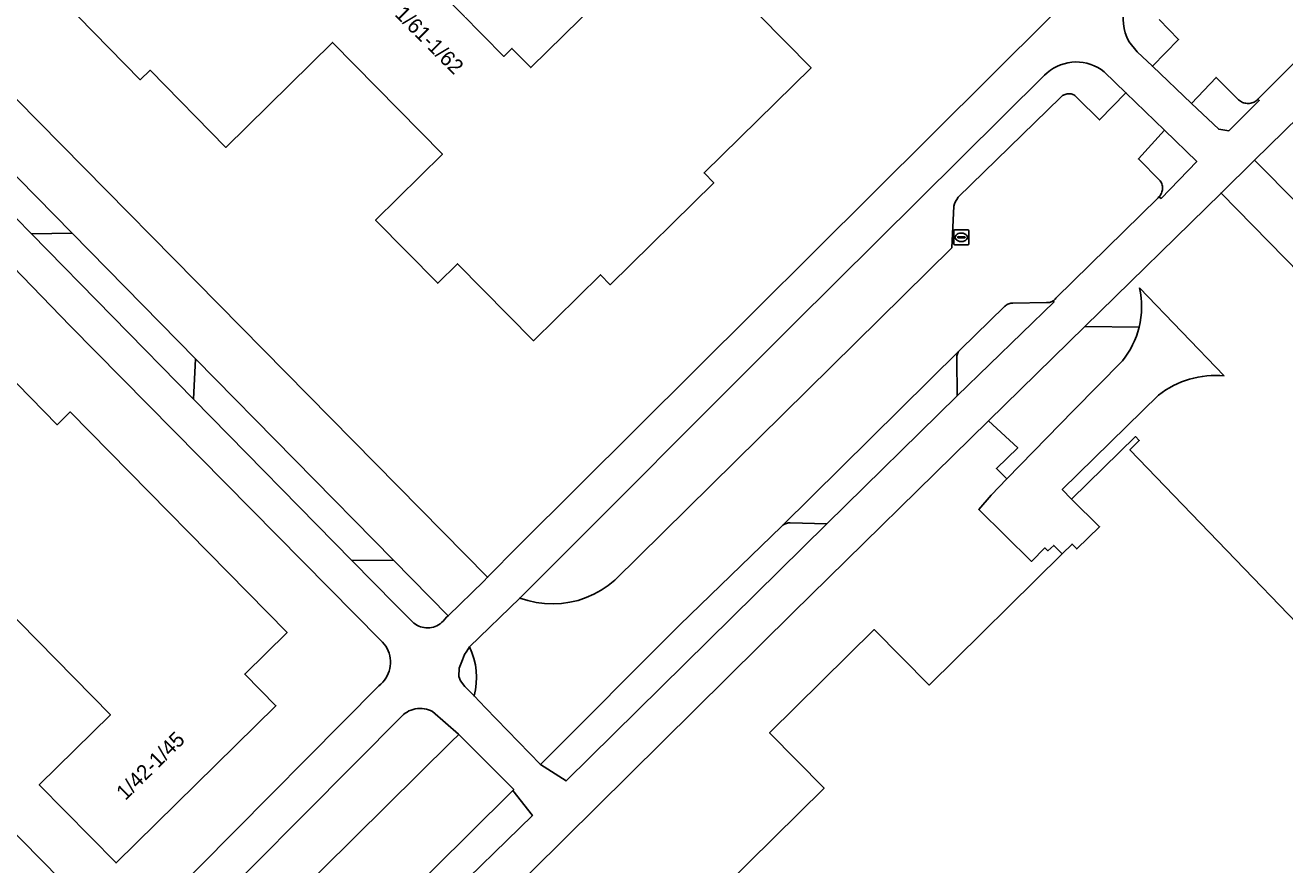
# Model space of a CAD drawing. Extents: x 162788 to 163838, y 385791 to 386523.
# Drawn here: x 163008.9 to 163092.2, y 386015.9 to 386071.5 of the extents above; entities that cross this region are included whole.
import ezdxf

# ---------------------------------------------------------------- set-up
doc = ezdxf.new("R2010")
doc.units = 0
for name, color, linetype in [('IMGEO_Berm_groen', 7, 'Continuous'), ('IMGEO_Erf', 7, 'Continuous'), ('IMGEO_Groenvoorziening', 7, 'Continuous'), ('IMGEO_Kolk', 7, 'Continuous'), ('IMGEO_Pand', 7, 'Continuous'), ('IMGEO_Pand_nummerreeks', 7, 'Continuous'), ('IMGEO_Parkeervlak_open', 7, 'Continuous'), ('IMGEO_Rijbaan_lokaal_gesloten', 7, 'Continuous'), ('IMGEO_Voetpad_gesloten', 7, 'Continuous'), ('IMGEO_Voetpad_open', 7, 'Continuous'), ('IMGEO_Woonerf_gesloten', 7, 'Continuous'), ('IMGEO_Woonerf_open', 7, 'Continuous')]:
    doc.layers.add(name, color=color, linetype=linetype)

msp = doc.modelspace()

# ---------------------------------------------------------------- linework, layer by layer
at = {"layer": 'IMGEO_Berm_groen'}
msp.add_lwpolyline([(163081.553, 386071.573), (163081.602, 386071.274), (163081.677, 386070.98), (163081.777, 386070.695), (163081.902, 386070.419), (163082.458, 386069.732), (163083.469, 386068.773), (163085.202, 386070.551), (163083.912, 386071.86)], dxfattribs=at)
for points in [[(163070.202, 386056.756), (163070.331, 386059.512), (163070.38, 386059.668), (163070.443, 386059.819), (163070.52, 386059.963), (163070.61, 386060.1), (163077.381, 386066.695), (163077.426, 386066.743), (163077.475, 386066.786), (163077.527, 386066.825), (163077.583, 386066.86), (163077.641, 386066.889), (163077.702, 386066.912), (163077.765, 386066.931), (163077.829, 386066.943), (163077.893, 386066.95), (163077.959, 386066.951), (163078.024, 386066.946), (163078.088, 386066.935), (163078.151, 386066.919), (163078.213, 386066.897), (163078.272, 386066.87), (163078.329, 386066.837), (163078.382, 386066.8), (163078.432, 386066.758), (163078.478, 386066.712), (163078.52, 386066.661), (163079.964, 386065.225), (163081.713, 386067.014), (163080.274, 386068.409), (163080.069, 386068.559), (163079.851, 386068.691), (163079.622, 386068.803), (163079.385, 386068.896), (163079.141, 386068.967), (163078.891, 386069.017), (163078.638, 386069.046), (163078.384, 386069.053), (163078.13, 386069.038), (163077.878, 386069.001), (163077.63, 386068.942), (163077.388, 386068.862), (163077.154, 386068.762), (163076.929, 386068.642), (163076.716, 386068.503), (163076.515, 386068.346), (163076.329, 386068.173), (163059.717, 386051.709), (163041.612, 386033.574), (163042.146, 386033.404), (163042.692, 386033.282), (163043.247, 386033.21), (163043.807, 386033.188), (163044.366, 386033.217), (163044.92, 386033.296), (163045.465, 386033.425), (163045.996, 386033.602), (163046.509, 386033.827), (163046.999, 386034.096), (163047.464, 386034.409), (163047.898, 386034.762)], [(163090.544, 386066.502), (163090.455, 386066.592), (163090.397, 386066.537), (163090.335, 386066.487), (163090.269, 386066.443), (163090.2, 386066.405), (163090.127, 386066.373), (163090.052, 386066.347), (163089.975, 386066.328), (163089.897, 386066.316), (163089.817, 386066.31), (163089.738, 386066.311), (163089.659, 386066.319), (163089.581, 386066.334), (163089.505, 386066.355), (163089.43, 386066.383), (163089.359, 386066.418), (163089.29, 386066.458), (163089.226, 386066.504), (163089.165, 386066.555), (163087.688, 386068.031), (163086.067, 386066.309), (163087.864, 386064.604), (163088.52, 386064.502)], [(163011.984, 386057.726), (163009.288, 386057.681), (163020.029, 386046.733), (163020.157, 386049.405)], [(163076.959, 386053.172), (163076.892, 386053.241), (163076.836, 386053.209), (163076.777, 386053.182), (163076.716, 386053.161), (163076.653, 386053.146), (163076.589, 386053.136), (163076.524, 386053.132), (163076.46, 386053.133), (163074.242, 386053.096), (163074.175, 386053.096), (163074.107, 386053.089), (163074.041, 386053.077), (163073.976, 386053.058), (163073.913, 386053.033), (163073.852, 386053.003), (163073.795, 386052.967), (163073.741, 386052.926), (163073.691, 386052.88), (163070.77, 386050.027), (163070.725, 386049.986), (163070.684, 386049.942), (163070.647, 386049.894), (163070.615, 386049.843), (163070.587, 386049.79), (163070.564, 386049.734), (163070.547, 386049.676), (163070.534, 386049.617), (163070.527, 386049.557), (163070.525, 386049.497), (163070.529, 386049.437), (163070.559, 386046.967)], [(163061.924, 386038.49), (163059.506, 386038.552), (163059.441, 386038.551), (163059.377, 386038.545), (163059.313, 386038.533), (163059.25, 386038.516), (163059.189, 386038.494), (163059.13, 386038.466), (163059.074, 386038.434), (163059.021, 386038.397), (163058.971, 386038.356), (163058.924, 386038.31), (163052.198, 386031.811), (163042.973, 386022.551), (163044.671, 386021.477)], [(163033.251, 386036.073), (163030.49, 386036.072), (163033.386, 386033.12), (163034.598, 386031.917), (163034.699, 386031.844), (163034.806, 386031.78), (163034.918, 386031.725), (163035.034, 386031.68), (163035.154, 386031.645), (163035.276, 386031.621), (163035.4, 386031.607), (163035.524, 386031.604), (163035.649, 386031.612), (163035.772, 386031.631), (163035.893, 386031.66), (163036.011, 386031.699), (163036.126, 386031.748), (163036.235, 386031.807), (163036.34, 386031.876), (163036.437, 386031.953), (163036.528, 386032.038), (163036.763, 386032.307), (163036.859, 386032.401)], [(163037.097, 386024.076), (163037.572, 386024.546), (163037.56, 386024.557), (163035.844, 386026.06), (163035.711, 386026.125), (163035.573, 386026.179), (163035.431, 386026.22), (163035.286, 386026.249), (163035.139, 386026.265), (163034.991, 386026.269), (163034.844, 386026.26), (163034.697, 386026.239), (163034.553, 386026.205), (163034.413, 386026.159), (163034.276, 386026.101), (163034.146, 386026.031), (163034.022, 386025.951), (163033.905, 386025.86), (163000.759, 385992.514), (163001.163, 385990.386), (163002.722, 385990.111), (163003.107, 385990.494), (163013.512, 386000.753)], [(163042.44, 386019.195), (163041.15, 386020.839), (163040.955, 386020.636), (163030.909, 386010.698), (163030.859, 386010.653), (163030.812, 386010.603), (163030.77, 386010.55), (163030.734, 386010.493), (163030.702, 386010.434), (163030.676, 386010.371), (163030.656, 386010.306), (163030.641, 386010.24), (163030.633, 386010.173), (163030.584, 386007.63)]]:
    msp.add_lwpolyline(points, close=True, dxfattribs=at)
at = {"layer": 'IMGEO_Erf'}
for points in [[(163144.69, 386116.333), (163116.889, 386088.826), (163094.139, 386066.379), (163090.229, 386062.548), (163093.084, 386059.675), (163106.347, 386045.615), (163117.907, 386034.052), (163120.625, 386031.361)], [(163034.593, 386105.372), (163032.927, 386102.387), (163031.643, 386100.544), (163030.645, 386099.338), (163027.569, 386096.044), (163022.475, 386091.076), (163020.687, 386089.641), (163019.2, 386088.539), (163019.01, 386088.395), (163017.057, 386087.161), (163014.761, 386086.098), (163012.296, 386085.312), (163009.878, 386084.654), (163007.401, 386084.184), (162993.768, 386081.986), (162993.461, 386081.653), (163039.475, 386034.95), (163041.516, 386037.028), (163076.704, 386072.029), (163076.476, 386072.907), (163056.429, 386093.317), (163049.21, 386100.56), (163041.713, 386107.825)], [(163036.379, 386073.667), (163040.55, 386069.424), (163041.089, 386069.954), (163042.334, 386068.688), (163053.16, 386079.329)], [(162996.592, 385991.771), (163032.285, 386027.77), (163032.418, 386027.879), (163032.54, 386028), (163032.652, 386028.132), (163032.751, 386028.272), (163032.837, 386028.421), (163032.91, 386028.577), (163032.969, 386028.739), (163033.013, 386028.905), (163033.042, 386029.075), (163033.057, 386029.246), (163033.056, 386029.418), (163033.04, 386029.59), (163033.008, 386029.759), (163032.962, 386029.925), (163032.902, 386030.086), (163032.827, 386030.241), (163032.739, 386030.389), (163032.639, 386030.529), (163032.526, 386030.659), (163032.402, 386030.778), (163011.849, 386051.6), (162989.767, 386074.455)], [(163055.694, 386073.954), (163060.889, 386068.669), (163053.807, 386061.708), (163054.447, 386061.057), (163047.59, 386054.316), (163046.949, 386054.968), (163042.506, 386050.601), (163037.494, 386055.7), (163036.181, 386054.41), (163032.067, 386058.596), (163036.488, 386062.942), (163029.212, 386070.345), (163022.152, 386063.405), (163017.14, 386068.505), (163016.498, 386067.874), (163012.383, 386072.06)], [(163122.643, 386025), (163088.018, 386060.382), (163078.994, 386051.539), (163082.592, 386051.498)], [(163082.621, 386054.105), (163088.226, 386048.292)], [(163005.665, 386050.481), (163011.004, 386045.049), (163011.867, 386045.897), (163026.216, 386031.299), (163023.413, 386028.544), (163025.477, 386026.444), (163014.893, 386016.042), (163009.811, 386021.212), (163014.518, 386025.839), (163003.657, 386036.889)], [(163083.877, 386047.013), (163077.501, 386040.771), (163078.117, 386040.121), (163082.342, 386044.263), (163082.601, 386043.999), (163081.98, 386043.39), (163100.049, 386024.635), (163100.685, 386025.264), (163100.884, 386025.064), (163097.686, 386021.901), (163097.949, 386021.634), (163096.965, 386020.661), (163095.449, 386022.194), (163093.939, 386020.701), (163094.444, 386020.19), (163094.075, 386019.826), (163096.492, 386017.373), (163085.965, 386006.999)], [(163007.393, 386018.836), (163012.476, 386013.665), (163001.892, 386003.263)]]:
    msp.add_lwpolyline(points, dxfattribs=at)
msp.add_lwpolyline([(163061.746, 386020.997), (163058.142, 386024.659), (163065.054, 386031.485), (163068.699, 386027.817), (163077.495, 386036.498), (163076.937, 386037.062), (163076.555, 386036.707), (163076.343, 386036.894), (163075.467, 386036.004), (163071.974, 386039.437), (163072.8, 386040.377), (163073.83, 386041.473), (163073.15, 386042.156), (163074.556, 386043.508), (163072.634, 386045.307), (163059.673, 386032.606), (163033.75, 386006.932), (163036.486, 386004.135), (163037.717, 386005.376), (163041.793, 386001.29)], close=True, dxfattribs=at)
for centre, radius, start, end in [((163077.077, 386052.863), 5.682, 346.0989, 12.62645), ((163087.681, 386042.111), 6.205, 84.964, 127.81222)]:
    msp.add_arc(centre, radius, start, end, dxfattribs=at)
at = {"layer": 'IMGEO_Groenvoorziening'}
for points in [[(163084.267, 386064.538), (163082.539, 386062.644), (163083.993, 386061.186), (163084.033, 386061.12), (163084.066, 386061.051), (163084.094, 386060.979), (163084.115, 386060.905), (163084.129, 386060.83), (163084.136, 386060.753), (163084.137, 386060.676), (163084.13, 386060.6), (163084.117, 386060.524), (163084.097, 386060.45), (163084.07, 386060.378), (163084.037, 386060.308), (163083.998, 386060.242), (163083.954, 386060.18), (163083.903, 386060.122), (163084.05, 386060.025), (163086.405, 386062.464)], [(163038.278, 386030.352), (163038.096, 386030.051), (163037.955, 386029.835), (163037.813, 386029.483), (163037.603, 386028.931), (163037.585, 386028.375), (163037.683, 386028.105), (163037.978, 386027.715), (163038.58, 386027.1), (163038.673, 386027.507), (163038.728, 386027.92), (163038.746, 386028.337), (163038.727, 386028.754), (163038.669, 386029.167), (163038.575, 386029.573), (163038.444, 386029.97)]]:
    msp.add_lwpolyline(points, close=True, dxfattribs=at)
at = {"layer": 'IMGEO_Kolk'}
for p, q in [((163070.327, 386057.024), (163070.327, 386057.876)), ((163070.402, 386057.95), (163071.254, 386057.95)), ((163070.586, 386057.444), (163070.586, 386057.456)), ((163071.024, 386057.407), (163070.626, 386057.407)), ((163070.629, 386057.493), (163071.027, 386057.493)), ((163070.815, 386057.73), (163070.84, 386057.73)), ((163071.07, 386057.456), (163071.07, 386057.444)), ((163071.328, 386057.876), (163071.328, 386057.024)), ((163071.254, 386056.95), (163070.402, 386056.95)), ((163070.838, 386057.17), (163070.813, 386057.17))]:
    msp.add_line(p, q, dxfattribs=at)
for points in [[(163070.327, 386057.024), (163070.327, 386057.876)], [(163070.402, 386057.95), (163071.254, 386057.95)], [(163071.328, 386057.876), (163071.328, 386057.024)], [(163071.254, 386056.95), (163070.402, 386056.95)]]:
    msp.add_lwpolyline(points, dxfattribs=at)
for centre, radius, start, end in [((163070.404, 386057.874), 0.0765, 91.55205, 178.44795), ((163070.404, 386057.874), 0.0765, 91.55205, 178.44795), ((163070.626, 386057.453), 0.0403, 85.87752, 175.75265), ((163070.623, 386057.443), 0.0366, 178.93798, 274.71019), ((163071.027, 386057.45), 0.043, 264.86636, 352.45326), ((163071.031, 386057.455), 0.0386, 1.73085, 96.63898), ((163071.252, 386057.874), 0.0765, 1.55205, 88.44795), ((163071.252, 386057.874), 0.0765, 1.55205, 88.44795), ((163070.404, 386057.026), 0.0765, 181.55205, 268.44795), ((163070.404, 386057.026), 0.0765, 181.55205, 268.44795), ((163071.252, 386057.026), 0.0765, 271.55205, 358.44795), ((163071.252, 386057.026), 0.0765, 271.55205, 358.44795)]:
    msp.add_arc(centre, radius, start, end, dxfattribs=at)
for centre, major_axis, ratio, start_param, end_param in [((163070.814, 386057.45), (-0.387, 0.002), 0.722429, 4.712389, 7.853982), ((163070.839, 386057.45), (-0.39, 0.002), 0.717154, 1.570796, 4.712389)]:
    msp.add_ellipse(centre, major_axis=major_axis, ratio=ratio, start_param=start_param, end_param=end_param, dxfattribs=at)
at = {"layer": 'IMGEO_Pand'}
for points in [[(163053.16, 386079.329), (163042.334, 386068.688), (163041.089, 386069.954), (163040.55, 386069.424), (163036.379, 386073.667)], [(163012.383, 386072.06), (163016.498, 386067.874), (163017.14, 386068.505), (163022.152, 386063.405), (163029.212, 386070.345), (163036.488, 386062.942), (163032.067, 386058.596), (163036.181, 386054.41), (163037.494, 386055.7), (163042.506, 386050.601), (163046.949, 386054.968), (163047.59, 386054.316), (163054.447, 386061.057), (163053.807, 386061.708), (163060.889, 386068.669), (163055.694, 386073.954)], [(163003.657, 386036.889), (163014.518, 386025.839), (163009.811, 386021.212), (163014.893, 386016.042), (163025.477, 386026.444), (163023.413, 386028.544), (163026.216, 386031.299), (163011.867, 386045.897), (163011.004, 386045.049), (163005.665, 386050.481)], [(163100.049, 386024.635), (163081.98, 386043.39), (163082.601, 386043.999), (163082.342, 386044.263), (163078.117, 386040.121), (163079.971, 386038.291), (163078.469, 386036.828), (163078.153, 386037.148), (163077.495, 386036.498), (163068.699, 386027.817), (163065.054, 386031.485), (163058.142, 386024.659), (163061.746, 386020.997), (163041.793, 386001.29)], [(163001.892, 386003.263), (163012.476, 386013.665), (163007.393, 386018.836)]]:
    msp.add_lwpolyline(points, dxfattribs=at)
at = {"layer": 'IMGEO_Parkeervlak_open'}
for points in [[(162998.996, 386070.949), (162998.906, 386068.262), (163009.288, 386057.681), (163011.984, 386057.726)], [(163070.559, 386046.967), (163070.529, 386049.437), (163070.525, 386049.497), (163070.527, 386049.557), (163070.534, 386049.617), (163070.547, 386049.676), (163070.564, 386049.734), (163070.587, 386049.79), (163070.615, 386049.843), (163070.647, 386049.894), (163070.684, 386049.942), (163058.971, 386038.356), (163059.021, 386038.397), (163059.074, 386038.434), (163059.13, 386038.466), (163059.189, 386038.494), (163059.25, 386038.516), (163059.313, 386038.533), (163059.377, 386038.545), (163059.441, 386038.551), (163059.506, 386038.552), (163061.924, 386038.49)], [(163020.157, 386049.405), (163020.029, 386046.733), (163030.49, 386036.072), (163033.251, 386036.073)]]:
    msp.add_lwpolyline(points, close=True, dxfattribs=at)
at = {"layer": 'IMGEO_Rijbaan_lokaal_gesloten'}
msp.add_lwpolyline([(163120.625, 386031.361), (163117.907, 386034.052), (163106.347, 386045.615), (163093.084, 386059.675), (163090.229, 386062.548), (163088.018, 386060.382), (163122.643, 386025), (163124.372, 386023.234), (163124.87, 386022.725)], dxfattribs=at)
at = {"layer": 'IMGEO_Voetpad_gesloten'}
for points in [[(163088.226, 386048.292), (163082.621, 386054.105)], [(163081.485, 386049.279), (163078.257, 386045.985), (163073.83, 386041.473), (163072.8, 386040.377), (163071.974, 386039.437), (163075.467, 386036.004), (163076.343, 386036.894), (163076.555, 386036.707), (163076.937, 386037.062), (163077.495, 386036.498), (163078.153, 386037.148), (163078.469, 386036.828), (163079.971, 386038.291), (163078.117, 386040.121), (163077.501, 386040.771), (163083.877, 386047.013)]]:
    msp.add_lwpolyline(points, dxfattribs=at)
for centre, radius, start, end in [((163077.077, 386052.863), 5.682, 346.0989, 12.62645), ((163077.082, 386052.861), 5.676, 320.86977, 346.10346), ((163087.681, 386042.111), 6.205, 84.964, 127.81222)]:
    msp.add_arc(centre, radius, start, end, dxfattribs=at)
at = {"layer": 'IMGEO_Voetpad_open'}
msp.add_lwpolyline([(163082.592, 386051.498), (163078.994, 386051.539), (163072.634, 386045.307), (163074.556, 386043.508), (163073.15, 386042.156), (163073.83, 386041.473), (163078.257, 386045.985), (163081.485, 386049.279)], dxfattribs=at)
msp.add_arc((163077.082, 386052.861), 5.676, 320.86977, 346.10346, dxfattribs=at)
at = {"layer": 'IMGEO_Woonerf_gesloten'}
for points in [[(163033.75, 386006.932), (163059.673, 386032.606), (163072.634, 386045.307), (163078.994, 386051.539), (163088.018, 386060.382), (163090.229, 386062.548), (163094.139, 386066.379), (163116.889, 386088.826), (163144.69, 386116.333)], [(163097.552, 386073.701), (163090.455, 386066.592), (163090.544, 386066.502), (163088.52, 386064.502), (163087.864, 386064.604), (163086.067, 386066.309), (163083.469, 386068.773), (163082.458, 386069.732), (163081.902, 386070.419), (163081.777, 386070.695), (163081.677, 386070.98), (163081.602, 386071.274), (163081.553, 386071.573), (163081.53, 386071.874), (163081.534, 386072.177), (163081.564, 386072.478), (163081.621, 386072.776), (163081.703, 386073.067), (163081.81, 386073.35), (163081.942, 386073.623), (163082.097, 386073.883), (163082.274, 386074.129), (163082.472, 386074.358), (163097.035, 386089.065)], [(162989.767, 386074.455), (163011.849, 386051.6), (163032.402, 386030.778), (163032.526, 386030.659), (163032.639, 386030.529), (163032.739, 386030.389), (163032.827, 386030.241), (163032.902, 386030.086), (163032.962, 386029.925), (163033.008, 386029.759), (163033.04, 386029.59), (163033.056, 386029.418), (163033.057, 386029.246), (163033.042, 386029.075), (163033.013, 386028.905), (163032.969, 386028.739), (163032.91, 386028.577), (163032.837, 386028.421), (163032.751, 386028.272), (163032.652, 386028.132), (163032.54, 386028), (163032.418, 386027.879), (163032.285, 386027.77), (162996.592, 385991.771)], [(163076.704, 386072.029), (163041.516, 386037.028), (163039.475, 386034.95), (163039.227, 386034.698), (163036.859, 386032.401), (163036.763, 386032.307), (163036.528, 386032.038), (163036.437, 386031.953), (163036.34, 386031.876), (163036.235, 386031.807), (163036.126, 386031.748), (163036.011, 386031.699), (163035.893, 386031.66), (163035.772, 386031.631), (163035.649, 386031.612), (163035.524, 386031.604), (163035.4, 386031.607), (163035.276, 386031.621), (163035.154, 386031.645), (163035.034, 386031.68), (163034.918, 386031.725), (163034.806, 386031.78), (163034.699, 386031.844), (163034.598, 386031.917), (163033.386, 386033.12), (163030.49, 386036.072), (163020.029, 386046.733), (163009.288, 386057.681), (162998.906, 386068.262)], [(163000.759, 385992.514), (163033.905, 386025.86), (163034.022, 386025.951), (163034.146, 386026.031), (163034.276, 386026.101), (163034.413, 386026.159), (163034.553, 386026.205), (163034.697, 386026.239), (163034.844, 386026.26), (163034.991, 386026.269), (163035.139, 386026.265), (163035.286, 386026.249), (163035.431, 386026.22), (163035.573, 386026.179), (163035.711, 386026.125), (163035.844, 386026.06), (163037.56, 386024.557), (163037.572, 386024.546), (163041.212, 386020.904), (163041.15, 386020.839), (163042.44, 386019.195), (163030.584, 386007.63)]]:
    msp.add_lwpolyline(points, dxfattribs=at)
msp.add_lwpolyline([(163059.717, 386051.709), (163076.329, 386068.173), (163076.515, 386068.346), (163076.716, 386068.503), (163076.929, 386068.642), (163077.154, 386068.762), (163077.388, 386068.862), (163077.63, 386068.942), (163077.878, 386069.001), (163078.13, 386069.038), (163078.384, 386069.053), (163078.638, 386069.046), (163078.891, 386069.017), (163079.141, 386068.967), (163079.385, 386068.896), (163079.622, 386068.803), (163079.851, 386068.691), (163080.069, 386068.559), (163080.274, 386068.409), (163081.713, 386067.014), (163084.267, 386064.538), (163086.405, 386062.464), (163084.05, 386060.025), (163083.903, 386060.122), (163083.848, 386060.068), (163077.082, 386053.415), (163077.041, 386053.365), (163076.995, 386053.319), (163076.945, 386053.278), (163076.892, 386053.241), (163076.959, 386053.172), (163070.559, 386046.967), (163061.924, 386038.49), (163044.671, 386021.477), (163042.973, 386022.551), (163039.336, 386026.317), (163038.58, 386027.1), (163037.978, 386027.715), (163037.683, 386028.105), (163037.585, 386028.375), (163037.603, 386028.931), (163037.813, 386029.483), (163037.955, 386029.835), (163038.096, 386030.051), (163038.278, 386030.352), (163041.612, 386033.574)], close=True, dxfattribs=at)
at = {"layer": 'IMGEO_Woonerf_open'}
for points in [[(162993.461, 386081.653), (162990.944, 386079.148), (162998.996, 386070.949), (163011.984, 386057.726), (163020.157, 386049.405), (163033.251, 386036.073), (163036.859, 386032.401), (163039.227, 386034.698), (163039.475, 386034.95)], [(163070.684, 386049.942), (163070.725, 386049.986), (163070.77, 386050.027), (163073.691, 386052.88), (163073.741, 386052.926), (163073.795, 386052.967), (163073.852, 386053.003), (163073.913, 386053.033), (163073.976, 386053.058), (163074.041, 386053.077), (163074.107, 386053.089), (163074.175, 386053.096), (163074.242, 386053.096), (163076.46, 386053.133), (163076.524, 386053.132), (163076.589, 386053.136), (163076.653, 386053.146), (163076.716, 386053.161), (163076.777, 386053.182), (163076.836, 386053.209), (163076.892, 386053.241), (163076.945, 386053.278), (163076.995, 386053.319), (163077.041, 386053.365), (163077.082, 386053.415), (163083.848, 386060.068), (163083.903, 386060.122), (163083.954, 386060.18), (163083.998, 386060.242), (163084.037, 386060.308), (163084.07, 386060.378), (163084.097, 386060.45), (163084.117, 386060.524), (163084.13, 386060.6), (163084.137, 386060.676), (163084.136, 386060.753), (163084.129, 386060.83), (163084.115, 386060.905), (163084.094, 386060.979), (163084.066, 386061.051), (163084.033, 386061.12), (163083.993, 386061.186), (163082.539, 386062.644), (163084.267, 386064.538), (163081.713, 386067.014), (163079.964, 386065.225), (163078.52, 386066.661), (163078.478, 386066.712), (163078.432, 386066.758), (163078.382, 386066.8), (163078.329, 386066.837), (163078.272, 386066.87), (163078.213, 386066.897), (163078.151, 386066.919), (163078.088, 386066.935), (163078.024, 386066.946), (163077.959, 386066.951), (163077.893, 386066.95), (163077.829, 386066.943), (163077.765, 386066.931), (163077.702, 386066.912), (163077.641, 386066.889), (163077.583, 386066.86), (163077.527, 386066.825), (163077.475, 386066.786), (163077.426, 386066.743), (163077.381, 386066.695), (163070.61, 386060.1), (163070.52, 386059.963), (163070.443, 386059.819), (163070.38, 386059.668), (163070.331, 386059.512), (163070.202, 386056.756), (163047.898, 386034.762), (163047.464, 386034.409), (163046.999, 386034.096), (163046.509, 386033.827), (163045.996, 386033.602), (163045.465, 386033.425), (163044.92, 386033.296), (163044.366, 386033.217), (163043.807, 386033.188), (163043.247, 386033.21), (163042.692, 386033.282), (163042.146, 386033.404), (163041.612, 386033.574), (163038.278, 386030.352), (163038.444, 386029.97), (163038.575, 386029.573), (163038.669, 386029.167), (163038.727, 386028.754), (163038.746, 386028.337), (163038.728, 386027.92), (163038.673, 386027.507), (163038.58, 386027.1), (163039.336, 386026.317), (163042.973, 386022.551), (163052.198, 386031.811), (163058.924, 386038.31), (163058.971, 386038.356)]]:
    msp.add_lwpolyline(points, close=True, dxfattribs=at)
for points in [[(163083.912, 386071.86), (163085.202, 386070.551), (163083.469, 386068.773), (163086.067, 386066.309), (163087.688, 386068.031), (163089.165, 386066.555), (163089.226, 386066.504), (163089.29, 386066.458), (163089.359, 386066.418), (163089.43, 386066.383), (163089.505, 386066.355), (163089.581, 386066.334), (163089.659, 386066.319), (163089.738, 386066.311), (163089.817, 386066.31), (163089.897, 386066.316), (163089.975, 386066.328), (163090.052, 386066.347), (163090.127, 386066.373), (163090.2, 386066.405), (163090.269, 386066.443), (163090.335, 386066.487), (163090.397, 386066.537), (163090.455, 386066.592), (163097.552, 386073.701)], [(163028.349, 386008.165), (163030.48, 386010.274), (163030.812, 386010.603), (163030.859, 386010.653), (163030.909, 386010.698), (163040.955, 386020.636), (163041.15, 386020.839), (163041.212, 386020.904), (163037.572, 386024.546), (163037.097, 386024.076), (163013.512, 386000.753), (163003.107, 385990.494), (163006.309, 385987.307), (163011.206, 385992.166)]]:
    msp.add_lwpolyline(points, dxfattribs=at)

# ---------------------------------------------------------------- texts
at = {"layer": 'IMGEO_Pand_nummerreeks'}
for s, rotation, p in [('1/61-1/62', 314.98959, (163033.277, 386072.153)), ('1/42-1/45', 44.71106, (163015.505, 386020.138))]:
    msp.add_text(s, height=1, rotation=rotation, dxfattribs=at).set_placement(p)

doc.saveas('drawing.dxf')
